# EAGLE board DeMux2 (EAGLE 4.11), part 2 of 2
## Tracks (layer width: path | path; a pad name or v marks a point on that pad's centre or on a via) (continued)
RCK  (via drill 0.61)  (1 unrouted) (continued)
  Bottom 0.381: IC10.12 206.38,131.44 207.65,130.18 229.24,130.18 230.5,131.44 IC12.12 231.78,132.72 233.04,133.99 246.38,133.99 248.28,132.08 304.8,132.08 306.7,133.99 319.4,133.99 | IC9.12 206.38,103.5 207.65,102.23 229.24,102.23 230.5,103.5 IC11.12 | v207.01,94.61 185.42,94.61 180.97,99.06 SV1.7 | 319.4,133.99 318.13,132.72 IC13.12 | 319.4,133.99 343.54,133.99 344.81,132.72 IC16.12 | 128.27,102.23 140.34,102.23 141.6,103.5 IC7.12 142.88,103.5 146.05,100.33 165.74,100.33 167,99.06 SV2.7 | 128.27,102.23 118.75,102.23 117.47,103.5 IC5.12 | IC1.12 33.66,131.44 34.92,130.18 56.52,130.18 57.78,131.44 IC4.12 59.05,132.72 60.33,133.99 118.75,133.99 | 118.75,133.99 117.47,132.72 IC6.12 | 118.75,133.99 140.34,133.99 141.6,132.72 IC8.12 | v128.27,104.78 128.27,102.23
RESET-TRIG#  (via drill 0.61)
  Top 0.381: v285.75,58.42 285.75,37.47 281.94,33.66 281.94,28.57 R23.1
  Bottom 0.381: v285.75,58.42 292.1,64.77 327.02,64.77 328.93,66.67 328.93,81.92 325.12,81.92 XESS.21
RS232-RD  (via drill 0.61)
  Top 0.381: D1.C 325.75,5.08 327.02,5.08 R2.1 327.66,5.71 328.93,6.99 v328.93,36.83
  Bottom 0.381: v328.93,36.83 304.17,36.83 302.89,38.1 XESS.31
RS232-RTS  (via drill 0.61)
  Top 0.381: v309.88,29.21 310.51,29.84 310.51,36.83 311.15,37.47 311.15,38.73 311.79,39.37 314.96,39.37 314.96,38.73 XESS.26
  Bottom 0.381: v309.88,29.21 253.37,29.21 252.09,27.94 R3.1
RS232-TD  (via drill 0.61)
  Top 0.381: v274.32,27.94 276.86,30.48 276.86,37.47 XESS.41
  Bottom 0.381: v274.32,27.94 273.05,26.67 250.82,26.67 249.56,25.4 R1.1
RTS
  Bottom 0.381: IC3.7 240.66,13.34 237.49,16.51 193.04,16.51 192.41,17.14 191.13,17.14 189.23,15.24 X1.8 189.87,14.61 192.41,14.61 196.85,10.16 RS-232.5
RUN
  Bottom 0.381: IC16.2 337.82,123.19 337.82,117.47 347.98,117.47 349.88,115.57 D40.33
RXD
  Bottom 0.381: IC3.8 243.21,12.06 241.94,10.79 212.09,10.79 210.19,12.7 199.39,12.7 RS-232.4 196.85,12.7 195.58,12.7 192.41,15.88 X1.3
SC0
  Bottom 0.381: IC1.1 23.5,123.83 30.48,116.84 32.38,116.84 33.66,115.57 C40.9
SC1
  Top 0.381: IC1.3 27.94,123.19 25.4,120.65 25.4,114.94 24.13,113.67 C40.2
SC2
  Bottom 0.381: IC1.5 33.66,125.09 34.92,126.36 38.73,126.36 39.37,125.73 39.37,116.84 50.16,116.84 51.44,115.57 C40.23
SC3
  Top 0.381: IC1.7 38.1,123.19 38.1,114.94 36.83,113.67 C40.12
SC4
  Bottom 0.381: IC4.1 48.9,125.09 50.16,126.36 64.14,126.36 64.77,125.73 64.77,116.2 C40.33
SCL\  (via drill 0.61)  (1 unrouted)
  Top 0.381: IC9.10 210.82,105.41 v210.82,107.31 210.82,111.12 209.55,112.39 209.55,129.54 210.82,130.81 IC10.10 | v240.03,109.22 240.03,128.27 | 240.03,128.27 240.03,133.99 238.12,133.99 236.85,132.72 IC12.10 | IC17.9 297.18,13.97 297.18,19.05 IC17.12 | v325.75,128.91 323.85,130.81 | 323.85,130.81 323.21,131.44 IC13.10 | v314.96,17.78 316.23,19.05 316.23,29.84 323.85,37.47 323.85,130.81 | 240.03,128.27 v243.84,128.27 | 53.98,111.76 53.34,112.39 53.34,116.84 38.73,131.44 IC1.10 | 53.98,111.76 67.31,111.76 67.31,128.27 64.14,131.44 IC4.10 | IC5.10 121.92,105.41 123.19,106.68 123.19,129.54 121.92,130.81 IC6.10 122.56,132.72 v125.09,135.25 | SV2.5 167,101.6 167,100.33 151.13,100.33 147.96,103.5 IC7.10 147.32,105.41 147.32,109.22 146.05,110.49 146.05,116.84 143.51,119.38 143.51,125.73 138.43,130.81 138.43,133.99 145.41,133.99 146.69,132.72 IC8.10 | 53.98,111.76 47.62,105.41 47.62,30.48 49.53,28.57 49.53,22.86 50.8,21.59 IC15.1
  Bottom 0.381: v240.03,109.22 236.22,105.41 IC11.10 235.59,104.78 233.04,107.31 v210.82,107.31 193.04,107.31 191.13,105.41 179.07,105.41 179.07,103.5 180.34,102.23 SV1.5 | IC16.10 349.88,131.44 347.35,128.91 v325.75,128.91 325.12,128.27 v243.84,128.27 | v314.96,17.78 302.26,17.78 297.81,13.34 IC17.9 | IC14.1 23.5,20.95 24.77,22.23 41.91,22.23 43.81,20.32 50.16,20.32 IC15.1 51.44,20.95 52.7,22.23 76.2,22.23 78.11,20.32 80.64,20.32 IC18.1 81.92,20.95 83.19,22.23 103.5,22.23 105.41,20.32 108.58,20.32 IC2.1 | IC8.10 146.69,132.72 144.15,135.25 v125.09,135.25 41.27,135.25 38.73,132.72 IC1.10
SCLK  (via drill 0.61)  (1 unrouted)
  Top 0.381: v288.29,57.15 288.29,15.24 287.02,13.97 IC17.5
  Bottom 0.381: 51.44,18.41 27.3,18.41 26.04,19.68 IC14.2 | 51.44,18.41 52.7,19.68 IC15.2 | 81.92,18.41 83.19,19.68 IC18.2 | 81.92,18.41 51.44,18.41 | 109.86,18.41 111.12,19.68 IC2.2 | 109.86,18.41 81.92,18.41 | 109.86,18.41 130.18,18.41 130.18,60.96 165.1,95.89 SV2.10 | v288.29,57.15 217.81,57.15 178.44,96.52 SV1.10
SD-CD#  (via drill 0.61)
  Top 0.381: v255.91,6.35 250.19,12.06 250.19,23.5 250.82,24.13 254,24.13 | 254,24.13 254,23.5 R4.1 | v267.97,81.28 269.24,80.01 269.24,50.16 257.81,38.73 257.81,31.11 254,27.3 254,24.13
  Bottom 0.381: v255.91,6.35 266.7,6.35 270.51,2.54 337.19,2.54 339.09,4.45 347.98,4.45 J4.10 | v267.97,81.28 280.04,81.28 281.31,82.55 XESS.4
SD-CLK  (via drill 0.61)
  Top 0.381: v323.85,14.61 318.77,14.61 318.77,6.99 314.32,2.54 280.67,2.54 280.67,21.59 278.13,24.13 278.13,65.41 274.95,68.58 274.95,81.92 XESS.1
  Bottom 0.381: v323.85,14.61 325.75,14.61 327.02,13.34 347.98,13.34 J4.5
SD-CMD
  Bottom 0.381: J4.2 347.98,21.59 339.73,21.59 325.75,35.56 269.88,35.56 267.33,38.1 XESS.45
SD-DAT0  (via drill 0.61)
  Top 0.381: v343.54,9.53 337.82,15.24 v337.82,54.61 | v229.24,54.61 226.06,57.78 226.06,81.92 XESS.66
  Bottom 0.381: v343.54,9.53 347.98,9.53 J4.7 | v229.24,54.61 v337.82,54.61
SD-DAT1  (via drill 0.61)
  Top 0.381: v232.41,53.34 228.6,57.15 228.6,81.92 XESS.67
  Bottom 0.381: v232.41,53.34 351.15,53.34 351.15,10.16 348.62,7.62 J4.8
SD-DAT2  (via drill 0.61)
  Top 0.381: v233.68,52.07 233.68,79.38 231.14,81.92 XESS.68
  Bottom 0.381: v233.68,52.07 335.28,52.07 335.28,37.47 347.98,24.77 J4.9
SD-DAT3  (via drill 0.61)
  Top 0.381: v234.95,48.26 234.95,80.64 233.68,81.92 XESS.69
  Bottom 0.381: v234.95,48.26 319.4,48.26 344.17,23.5 347.98,23.5 J4.1
SD-WP  (via drill 0.61)
  Top 0.381: v352.43,3.81 351.79,4.45 342.9,4.45 339.73,1.27 274.32,1.27 v274.32,3.81 | v273.69,76.2 273.05,75.56 273.05,36.83 255.27,19.05 255.27,12.06 254.63,11.43 252.09,11.43 252.09,12.7 R5.1
  Bottom 0.381: v352.43,3.81 365.12,3.81 367.03,1.91 J4.12 | v274.32,3.81 266.7,11.43 253.37,11.43 252.09,12.7 R5.1 | v273.69,76.2 277.5,76.2 283.85,82.55 XESS.5
SDF0
  Top 0.381: R24.1 38.1,32.38 38.1,31.75 35.56,29.21 IC14.11 35.56,26.67 35.56,22.86 34.29,21.59 34.29,8.89 32.38,8.89 31.11,10.16 A40.6
SDF1
  Top 0.381: R25.1 33.02,32.38 33.02,29.21 IC14.12 33.02,26.67 31.75,25.4 31.75,12.06 33.02,10.79 A40.8
SDF2
  Bottom 0.381: IC14.13 30.48,29.21 27.94,31.75 27.94,32.38 R26.1 27.3,33.02 26.04,34.29 17.78,34.29 17.78,20.95 24.13,14.61 30.48,14.61 34.92,10.16 A40.10
SI
  Top 0.381: R49.1 91.44,32.38 91.44,29.21 IC18.12 91.44,26.67 90.17,25.4 90.17,8.89 120.02,8.89 121.28,10.16 B40.32
SIF0
  Top 0.381: IC14.14 27.94,29.21 25.4,31.75 25.4,32.38 R27.1
  Bottom 0.381: A40.12 37.47,10.16 31.75,15.88 24.13,15.88 19.05,20.95 19.05,31.75 23.5,31.75 24.77,33.02 R27.1
SIF1
  Top 0.381: R28.1 22.86,32.38 24.13,31.11 24.13,25.4 27.94,21.59 IC14.3 27.94,19.05 29.21,17.78 29.21,6.35 36.2,6.35 36.83,6.99 36.83,8.89 38.73,8.89 40.01,10.16 A40.14
SIF2  (via drill 0.61)
  Top 0.381: R29.1 30.48,32.38 29.21,31.11 29.21,22.86 30.48,21.59 IC14.4 30.48,19.05 v30.48,17.14
  Bottom 0.381: v30.48,17.14 35.56,17.14 42.55,10.16 A40.16
SLOT1-CS#  (via drill 0.61)
  Top 0.381: v318.77,111.76 318.77,84.45 317.5,83.19 XESS.18
  Bottom 0.381: v318.77,111.76 309.25,111.76 302.89,118.11 291.46,118.11 290.19,116.84 252.73,116.84 252.73,114.94 251.46,113.67 SLOT1.37
SLOT1-IRQ
  Top 0.381: R21.1 271.78,104.78 273.05,103.5 273.05,85.72 271.78,84.45 271.78,83.19 XESS.84
SLOT2-CS#  (via drill 0.61)
  Top 0.381: v252.73,80.01 252.73,93.34 251.46,94.61 SLOT2.37
  Bottom 0.381: v252.73,80.01 260.35,72.39 311.79,72.39 320.04,80.64 320.04,81.92 XESS.19
SLOT2-IRQ  (via drill 0.61)
  Top 0.381: v266.7,92.08 269.24,89.53 269.24,83.19 XESS.83
  Bottom 0.381: v266.7,92.08 255.27,92.08 255.27,98.42 248.92,104.78 R22.1
SR0
  Top 0.381: IC14.5 33.02,21.59 34.29,22.86 34.29,31.11 35.56,32.38 R30.1 35.56,33.66 35.56,34.29 38.73,34.29 39.37,33.66 39.37,32.38 44.45,27.3 44.45,12.06 45.72,10.79 A40.18
SR1
  Top 0.381: IC14.6 36.2,19.68 43.18,12.7 43.18,12.06 44.45,10.79 44.45,9.53 45.09,8.89 47.62,8.89 47.62,10.16 A40.20 48.26,10.79 46.35,12.7 46.35,33.02 41.27,33.02 R31.1
SR2  (via drill 0.61)
  Top 0.381: 64.77,30.48 66.04,31.75 66.04,32.38 R32.1 | 64.77,30.48 63.5,29.21 IC15.11 | v62.23,13.34 64.77,15.88 64.77,30.48
  Bottom 0.381: v62.23,13.34 59.69,13.34 56.52,10.16 A40.26
SR3
  Top 0.381: R33.1 60.96,32.38 60.96,29.21 IC15.12 60.96,26.67 59.69,25.4 59.69,12.06 58.42,10.79 A40.28
SR4  (via drill 0.61)
  Top 0.381: IC15.13 58.42,29.21 58.42,32.38 R34.1 | v54.61,24.77 54.61,8.89 59.05,8.89 60.33,10.16 A40.30
  Bottom 0.381: v54.61,24.77 55.88,26.04 56.52,26.04 57.78,27.3 IC15.13
SR5
  Top 0.381: IC15.14 55.88,29.21 53.34,31.75 53.34,32.38 R35.1 53.34,33.66 53.34,34.29 66.67,34.29 67.31,33.66 67.31,12.06 66.04,10.79 A40.34
SR6
  Top 0.381: 52.07,31.75 51.44,32.38 51.44,33.02 R36.1 | 52.07,31.75 54.61,29.21 54.61,26.67 55.88,25.4 55.88,21.59 IC15.3 | 52.07,31.75 52.07,6.35 61.59,6.35 62.23,6.99 62.23,8.26 63.5,9.53 A40.32
SR7  (via drill 0.61)
  Top 0.381: R37.1 55.88,32.38 57.15,31.11 57.15,22.86 58.42,21.59 IC15.4 58.42,19.05 v58.42,14.61
  Bottom 0.381: v58.42,14.61 83.82,14.61 88.27,10.16 B40.6
SR8  (via drill 0.61)
  Top 0.381: R38.1 63.5,32.38 62.23,31.11 62.23,22.86 60.96,21.59 IC15.5 60.96,19.05 60.96,17.78 v62.87,15.88
  Bottom 0.381: v62.87,15.88 85.09,15.88 90.81,10.16 B40.8
SR9  (via drill 0.61)
  Top 0.381: v63.5,24.77 63.5,21.59 IC15.6 63.5,19.05 v63.5,17.14
  Bottom 0.381: v63.5,24.77 64.77,26.04 66.67,26.04 67.31,26.67 67.31,33.02 67.94,33.02 R39.1 | v63.5,17.14 86.36,17.14 93.34,10.16 B40.10
SR10  (via drill 0.61)
  Top 0.381: 123.19,30.48 124.46,31.75 124.46,32.38 R40.1 | 123.19,30.48 121.92,29.21 IC2.11 | v121.92,17.14 123.19,18.41 123.19,30.48
  Bottom 0.381: v121.92,17.14 104.14,17.14 97.16,10.16 B40.12
SR11
  Top 0.381: IC2.12 119.38,29.21 119.38,32.38 R41.1 119.38,33.66 119.38,34.29 108.58,34.29 105.41,31.11 105.41,17.14 99.06,10.79 B40.14
SS  (via drill 0.61)
  Top 0.381: IC18.11 93.98,29.21 96.52,31.75 96.52,32.38 R48.1 | v128.91,33.02 128.91,15.24 124.46,10.79 B40.34
  Bottom 0.381: v128.91,33.02 127.64,34.29 98.42,34.29 97.16,33.02 R48.1
SSER  (via drill 0.61)  (1 unrouted)
  Top 0.381: v294,24.13 294,22.23 294.64,21.59 IC17.13 | v100.97,44.45 100.97,31.11 99.06,29.21 IC18.9
  Bottom 0.381: v294,24.13 274.95,24.13 272.42,21.59 245.11,21.59 229.87,36.83 220.34,36.83 176.53,80.64 176.53,99.06 177.16,99.06 SV1.8 | v100.97,44.45 155.57,99.06 164.47,99.06 SV2.8
START  (via drill 0.61)
  Top 0.381: v117.47,31.11 117.47,29.84 116.84,29.21 IC2.13 116.84,26.67 118.11,25.4 118.11,18.41 v115.57,15.88
  Bottom 0.381: v117.47,31.11 116.84,31.75 116.2,31.75 114.94,33.02 R42.1 | v115.57,15.88 107.95,15.88 102.23,10.16 B40.16
STOP
  Top 0.381: 120.65,13.97 120.65,12.06 119.38,10.79 B40.30 | 120.65,13.97 120.65,17.78 121.92,19.05 IC2.6 | 120.65,13.97 125.73,19.05 125.73,31.11 127,32.38 R47.1
TAD  (via drill 0.61)
  Top 0.381: v313.69,121.92 313.69,114.94 312.42,113.67 D40.4
  Bottom 0.381: v313.69,121.92 312.42,121.92 310.51,123.83 IC13.2
TXD
  Top 0.381: IC3.14 231.78,19.68 233.04,19.68 IC3.13
  Bottom 0.381: X1.2 192.41,18.41 193.04,17.78 196.85,17.78 RS-232.2 199.39,17.78 210.19,17.78 214.63,22.23 229.24,22.23 230.5,20.95 IC3.14
VCC  (via drill 0.61)  (1 unrouted)
  Top 0.762: R31.2 40.01,43.18 38.73,43.18 R24.2 37.47,43.18 36.2,43.18 R30.2 34.92,43.18 33.66,43.18 R25.2 32.38,43.18 31.11,43.18 R29.2 29.84,43.18 28.57,43.18 R26.2 27.3,43.18 26.04,43.18 R27.2 24.77,43.18 23.5,43.18 R28.2 22.86,42.55 20.95,40.64 20.95,31.11 22.86,29.21 IC14.16 | R39.2 67.94,43.18 66.67,43.18 R32.2 65.41,43.18 64.14,43.18 R38.2 62.87,43.18 61.59,43.18 R33.2 60.33,43.18 59.05,43.18 R34.2 57.78,43.18 56.52,43.18 R37.2 55.24,43.18 53.98,43.18 R35.2 52.7,43.18 51.44,43.18 R36.2 50.8,42.55 48.9,40.64 48.9,31.11 50.8,29.21 IC15.16 | R9.1 93.34,43.18 92.08,43.18 R49.2 | IC18.16 81.28,29.21 79.38,31.11 79.38,40.64 81.28,42.55 R6.1 | R43.2 109.86,43.18 111.12,43.18 R44.2 112.39,43.18 113.67,43.18 R42.2 114.94,43.18 116.2,43.18 R45.2 117.47,43.18 118.75,43.18 R41.2 120.02,43.18 121.28,43.18 R46.2 122.56,43.18 123.83,43.18 R40.2 125.09,43.18 126.36,43.18 R47.2 | v104.14,28.57 104.14,37.47 109.22,42.55 R43.2 | v156.21,107.95 156.21,107.31 152.4,103.5 C18.1 | v132.08,107.31 132.08,105.41 IC7.16 | +V3.1 163.19,120.65 153.03,130.81 C9.1 152.4,131.44 152.4,135.25 135.25,135.25 132.72,132.72 IC8.16 | 102.23,130.81 103.5,130.81 C8.1 | 102.23,130.81 69.22,130.81 C7.1 68.58,131.44 68.58,134.62 50.8,134.62 48.9,132.72 IC4.16 48.26,133.35 48.26,134.62 25.4,134.62 23.5,132.72 IC1.16 | 102.87,110.49 102.87,125.09 102.23,125.73 102.23,130.81 | 102.87,110.49 102.87,104.78 104.14,103.5 C16.1 | v106.68,108.58 106.68,105.41 IC5.16 | 102.87,110.49 100.33,107.95 100.33,92.71 103.5,89.53 103.5,49.53 109.22,43.81 R43.2 | C14.1 355.6,130.18 366.39,119.38 366.39,100.33 369.57,97.16 +V2.1
  Top 0.762: v332.74,127.64 332.74,128.27 335.28,130.81 IC16.16 | v309.88,135.25 309.88,134.62 307.98,132.72 IC13.16 | v223.52,100.97 223.52,101.6 221.62,103.5 IC11.16 | v241.3,135.25 241.3,131.44 C11.1 | C10.1 192.41,130.81 191.77,130.81 182.88,121.92 +V4.1 180.97,117.47 180.97,111.12 v189.23,102.87 189.23,58.42 226.06,21.59 IC3.16 | 5V.1 276.86,22.23 276.86,21.59 IC17.20 | 221.62,7.62 212.09,7.62 +V1.1 | 221.62,7.62 222.88,7.62 C1.1 | 221.62,7.62 221.62,16.51 223.52,18.41 C23.1 | v332.74,22.23 332.74,71.75 354.33,93.34 J1.4
  Bottom 0.762: C19.1 20.95,26.67 21.59,27.3 22.23,27.3 IC14.16 | C20.1 48.9,26.67 49.53,27.3 50.16,27.3 IC15.16 | R31.2 41.27,43.18 50.16,43.18 R36.2 | C21.1 79.38,26.67 80.01,27.3 80.64,27.3 IC18.16 | R49.2 90.81,43.18 89.53,43.18 R8.1 88.27,43.18 87,43.18 R50.1 85.72,43.18 84.45,43.18 R7.1 83.19,43.18 81.92,43.18 R6.1 80.64,43.18 69.22,43.18 R39.2 | R9.1 94.61,43.18 95.89,43.18 R48.2 97.16,43.18 98.42,43.18 R10.1 99.69,43.18 108.58,43.18 R43.2 | IC2.16 108.58,27.3 107.95,27.3 107.31,26.67 C22.1 106.05,26.67 v104.14,28.57 | +V3.1 165.74,117.47 v156.21,107.95 155.57,107.31 v132.08,107.31 130.81,108.58 v106.68,108.58 | C16.1 104.78,102.87 105.41,103.5 106.05,103.5 IC5.16 | C6.1 20.95,130.81 21.59,131.44 22.23,131.44 IC1.16 | IC6.16 106.05,131.44 105.41,130.81 104.78,130.81 C8.1 | C12.1 305.44,130.81 306.07,131.44 306.7,131.44 IC13.16 | v332.74,127.64 351.79,127.64 354.96,130.81 C14.1 355.6,131.44 355.6,132.08 352.43,135.25 v309.88,135.25 | J1.4 356.87,93.34 367.67,93.34 +V2.1 | C13.1 193.68,102.87 194.31,103.5 194.94,103.5 IC9.16 | C15.1 240.66,102.87 238.76,100.97 v223.52,100.97 222.88,100.33 194.94,100.33 193.04,102.23 C13.1 | C10.1 193.68,130.81 194.31,131.44 194.94,131.44 IC10.16 196.22,132.72 198.75,135.25 217.81,135.25 | 217.81,135.25 220.34,132.72 IC12.16 | 217.81,135.25 v241.3,135.25 | v189.23,102.87 192.41,102.87 C13.1 | IC19.14 309.25,19.68 308.61,19.68 307.98,19.05 C17.1 306.7,19.05 302.89,22.86 | IC17.20 276.23,19.68 275.59,19.68 274.95,19.05 C24.1 273.69,19.05 273.05,19.68 245.75,19.68 243.84,17.78 228.6,17.78 226.69,19.68 IC3.16 225.43,19.68 224.79,19.68 224.16,19.05 C23.1
  Bottom 0.762: 302.89,22.86 277.5,22.86 5V.1 | v332.74,22.23 332.11,22.86 302.89,22.86
VDD  (via drill 0.61)
  Top 0.762: v311.79,31.75 v314.32,29.21 | v260.99,31.75 257.18,27.94 3.3V.2
  Bottom 0.762: v314.32,29.21 327.66,29.21 340.36,16.51 347.98,16.51 J4.4 | v260.99,31.75 v311.79,31.75
VSS  (via drill 0.61)
  Top 0.762: v339.73,3.17 346.07,9.53 v346.07,10.79
  Bottom 0.762: J4.3 348.62,19.68 349.88,19.68 349.88,12.06 349.25,11.43 348.62,11.43 J4.6 347.98,10.79 v346.07,10.79 | v339.73,3.17 337.82,1.27 269.88,1.27 266.06,5.08 252.09,5.08 J3.1
WC
  Top 0.381: IC16.5 345.44,123.19 344.17,121.92 344.17,114.94 345.44,113.67 D40.30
